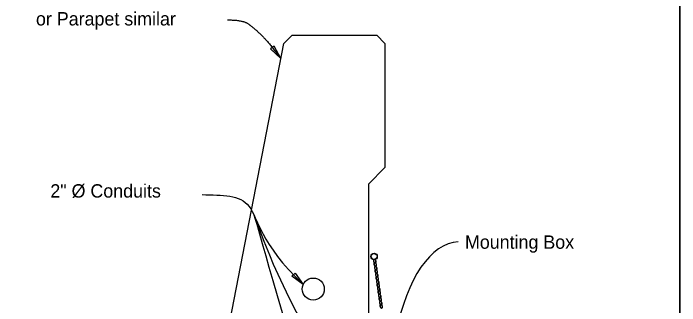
# Model space of a CAD drawing. Extents: x 0 to 20.5, y 0 to 13.
# Drawn here: x 15.49 to 20.53, y 6.43 to 8.64 of the extents above; entities that cross this region are included whole.
import ezdxf

# ---------------------------------------------------------------- set-up
doc = ezdxf.new("R2010")
doc.units = 0
for name, color, linetype in [('ActivePts-ConstElements', 7, 'Continuous'), ('Dimension', 7, 'Continuous'), ('Miscellaneous', 7, 'Continuous'), ('Miscellaneous1', 7, 'Continuous'), ('NavLight', 7, 'Continuous'), ('TextStructures', 7, 'Continuous'), ('TrafBarrierConc', 7, 'Continuous')]:
    doc.layers.add(name, color=color, linetype=linetype)

msp = doc.modelspace()

# ---------------------------------------------------------------- linework, layer by layer
at = {"layer": 'ActivePts-ConstElements'}
msp.add_lwpolyline([(0, 0), (20.5253, 0), (20.5253, 12.9731), (0, 12.9731)], close=True, dxfattribs=at)
at = {"layer": 'Dimension'}
for points in [[(17.5141, 8.2993), (17.4647, 8.3927), (17.4367, 8.3712)], [(17.622, 6.6794), (17.6826, 6.5929), (17.5969, 6.6546)]]:
    msp.add_lwpolyline(points, close=True, dxfattribs=at)
msp.add_ellipse((18.9015, 5.6333), major_axis=(0.0485, -1.2809), ratio=0.439724, start_param=3.141585, end_param=4.215808, dxfattribs=at)
for points, degree in [([(17.1105, 8.59), (17.2268, 8.59), (17.3075, 8.5319), (17.4076, 8.4382), (17.5141, 8.2993)], 2), ([(16.9195, 7.2717), (17.0736, 7.2661), (17.3355, 7.2787), (17.3509, 6.908), (17.6826, 6.5929)], 3), ([(16.9195, 7.2717), (17.0736, 7.2661), (17.3355, 7.2787), (17.3509, 6.908), (17.675, 5.8915)], 3), ([(16.9195, 7.2717), (17.0736, 7.2661), (17.3355, 7.2787), (17.3509, 6.908), (17.6899, 6.2723)], 3)]:
    msp.add_open_spline(points, degree=degree, dxfattribs=at)
at = {"layer": 'Miscellaneous'}
for radius in [0.0241, 0.0222]:
    msp.add_circle((18.218, 6.8045), radius, dxfattribs=at)
for centre, major_axis, ratio in [((18.2229, 6.7693), (-0.0022, 0.0152), 0.530594), ((18.2229, 6.7693), (-0.0019, 0.0131), 0.458548), ((18.2267, 6.743), (-0.0022, 0.0152), 0.530594), ((18.2267, 6.743), (-0.0019, 0.0131), 0.458548), ((18.2305, 6.7167), (-0.0022, 0.0152), 0.530594), ((18.2305, 6.7167), (-0.0019, 0.0131), 0.458548), ((18.2343, 6.6904), (-0.0022, 0.0152), 0.530594), ((18.2343, 6.6904), (-0.0019, 0.0131), 0.458548), ((18.238, 6.6641), (-0.0022, 0.0152), 0.530594), ((18.238, 6.6641), (-0.0019, 0.0131), 0.458548), ((18.2418, 6.6378), (-0.0022, 0.0152), 0.530594), ((18.2418, 6.6378), (-0.0019, 0.0131), 0.458548), ((18.2456, 6.6116), (-0.0022, 0.0152), 0.530594), ((18.2456, 6.6116), (-0.0019, 0.0131), 0.458548), ((18.2494, 6.5853), (-0.0022, 0.0152), 0.530594), ((18.2494, 6.5853), (-0.0019, 0.0131), 0.458548), ((18.2532, 6.559), (-0.0022, 0.0152), 0.530594), ((18.2532, 6.559), (-0.0019, 0.0131), 0.458548), ((18.257, 6.5327), (-0.0022, 0.0152), 0.530594), ((18.257, 6.5327), (-0.0019, 0.0131), 0.458548), ((18.2608, 6.5064), (-0.0022, 0.0152), 0.530594), ((18.2608, 6.5064), (-0.0019, 0.0131), 0.458548), ((18.2645, 6.4801), (-0.0022, 0.0152), 0.530594), ((18.2645, 6.4801), (-0.0019, 0.0131), 0.458548), ((18.2683, 6.4538), (-0.0022, 0.0152), 0.530594), ((18.2683, 6.4538), (-0.0019, 0.0131), 0.458548), ((18.2721, 6.4275), (-0.0022, 0.0152), 0.530594), ((18.2721, 6.4275), (-0.0019, 0.0131), 0.458548)]:
    msp.add_ellipse(centre, major_axis=major_axis, ratio=ratio, dxfattribs=at)
at = {"layer": 'Miscellaneous1'}
msp.add_lwpolyline([(0, 12.9731), (20.5253, 12.9731), (20.5253, 0), (0, 0)], close=True, dxfattribs=at)
at = {"layer": 'NavLight'}
msp.add_circle((17.7583, 6.5582), 0.0833, dxfattribs=at)
at = {"layer": 'TrafBarrierConc'}
for p, q in [((17.536, 8.4123), (17.5985, 8.4748)), ((17.5985, 8.4748), (18.2375, 8.4749)), ((18.2375, 8.4748), (18.3, 8.4123)), ((16.9667, 5.4749), (17.536, 8.4123)), ((18.3, 8.4123), (18.3, 7.4748)), ((18.3, 7.4748), (18.175, 7.3498)), ((18.175, 7.3498), (18.175, 5.4749))]:
    msp.add_line(p, q, dxfattribs=at)

# ---------------------------------------------------------------- texts
at = {"layer": 'Dimension'}
msp.add_text('or Parapet similar', height=0.1008, dxfattribs=at).set_placement((15.665, 8.548))
at = {"layer": 'TextStructures'}
for s, p in [('2" Ø Conduits', (15.7736, 7.249)), ('Mounting Box', (18.9041, 6.8628))]:
    msp.add_text(s, height=0.1008, dxfattribs=at).set_placement(p)

doc.saveas('drawing.dxf')
